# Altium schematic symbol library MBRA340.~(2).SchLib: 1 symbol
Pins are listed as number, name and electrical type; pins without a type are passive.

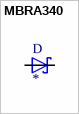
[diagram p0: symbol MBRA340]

## MBRA340
designator D
ãƒ€ã‚¤ã‚ªãƒ¼ãƒ‰ã‚·ãƒ§ãƒƒãƒˆã‚­ãƒ¼40V 3Aè¡¨é¢å®Ÿè£…SMA; MP: MBRA340; MF: ON Semiconductor
footprint SMA
pins: A, C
